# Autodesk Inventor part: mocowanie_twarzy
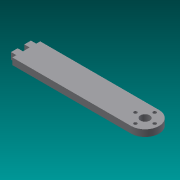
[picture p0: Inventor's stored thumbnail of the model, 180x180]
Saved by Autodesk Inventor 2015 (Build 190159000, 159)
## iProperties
Created: 2016-02
Part Number: mocowanie_twarzy
Material: Generic
Document SubType Name: Modeling
Designer: Rafał
Density: 1 g/cm^3
Appearance: Default
Author: Rafał
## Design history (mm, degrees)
sketch "Sketch1" dims "d3" = 14.5
  geometry: L1 (-10.5, 0)-(-100, 0); L2 (-100, 21)-(-10.5, 21); L3 (0, 21)-(0, 0); L4 (0, 10.5)-(-100, 10.5); L5 (0, 10.5)-(-10.5, 10.5); L6 (-100, 13)-(-104, 13); L7 (-104, 13)-(-104, 18); L8 (-104, 18)-(-100, 18); L9 (-100, 18)-(-100, 13); L10 (-100, 8)-(-104, 8); L11 (-104, 8)-(-104, 3); L12 (-104, 3)-(-100, 3); L13 (-100, 0)-(-100, 3); L14 (-100, 8)-(-100, 13); L15 (-100, 18)-(-100, 21); C1 r 1.25 at (-3.25, 10.5); C2 r 1.25 at (-10.5, 17.75); C3 r 1.25 at (-17.75, 10.5); C4 r 1.25 at (-10.5, 3.25); A1 r 10.5 centre (-10.5, 10.5) between (-10.5, 0) and (-10.5, 21); 1 further point
  constraints: 30 end point, 6 parallel, 5 centre point, 4 perpendicular, 4 symmetric about line, 3 point on circle, 2 coincident, 2 horizontal, 2 midpoint, 2 point on line, 1 horizontal alignment, 11 other
  dimensions: "d0" = 100 distance of L2.start L3.start; "d1" = 21 distance of L1.end L2.start; "d2" = 10.5 distance of L4.start L5.end; "d4" = 2.5 diameter of C1; "d7" = 360 deg dimension on L5.end C1.centre (derived); "d9" = 4 distance of L7.end L8.end; "d10" = 5 distance of L6.end L7.end; "d11" = 2.5 distance between parallel lines of L6 L4
extrude "Extrusion1" new body sketch "Sketch1" distance "d12" = 5; taper "d13" = 0 deg
sketch "Sketch2"
  geometry: L1 (-10.5, 3.25)-(-10.5, 17.75); L2 (-10.5, 17.75)-(-17.75, 10.5); L3 (-17.75, 10.5)-(-3.25, 10.5); C1 r 1.25 at (-10.5, 3.25) reference; C2 r 1.25 at (-10.5, 17.75) reference; C3 r 1.25 at (-17.75, 10.5) reference; C4 r 1.25 at (-3.25, 10.5) reference; C5 r 3.5 at (-10.5, 10.5); 1 further point
  constraints: 6 end point, 1 centre point, 1 midpoint, 1 perpendicular, 1 vertical
  dimensions: "d14" = 7 diameter of C5
extrude "Extrusion2" cut sketch "Sketch2" distance "d15" = 10; taper "d16" = 0 deg
body "Solid1"
